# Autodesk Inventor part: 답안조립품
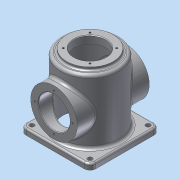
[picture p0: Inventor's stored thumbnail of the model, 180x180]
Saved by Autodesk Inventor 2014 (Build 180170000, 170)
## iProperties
Created: 2015-10
Part Number: 답안조립품
Material: 알루미늄 6061
Document SubType Name: Modeling
Designer: net
Density: 2.71 g/cm^3
Appearance: 알루미늄 - 평지
Mass: 985.994 g
Surface Area: 1037.34 cm^2
Volume: 363.835 cm^3
Author: net
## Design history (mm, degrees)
sketch "스케치1"
  geometry: L1 (60, -60)-(-60, -60); L2 (-60, -60)-(-60, 60); L3 (-60, 60)-(60, 60); L4 (60, 60)-(60, -60); L5 (60, 0)-(-60, 0); C1 r 4 at (50, -50); C2 r 4 at (-50, -50); C3 r 4 at (50, 50); C4 r 4 at (-50, 50); 2 further points
  constraints: 10 end point, 4 centre point, 3 midpoint, 2 horizontal alignment, 2 parallel, 2 perpendicular, 2 symmetric about line, 1 equal radius, 1 horizontal, 1 vertical alignment, 2 other
  dimensions: "d0" = 120 distance of L1.start L1.end; "d1" = 120 distance of L1.end L2.end; "d2" = 8 diameter of C1; "d3" = 50 horizontal distance of C1.centre point (0, 0); "d4" = 50 horizontal distance of point (0, 0) C1.centre; "d5" = 100 distance of C2.centre C1.centre
extrude "돌출1" new body sketch "스케치1" distance "d6" = 10; taper "d7" = 0 deg
fillet "모깎기1" dims "d8" = 10
node "작업 평면2"
sketch "스케치2"
  geometry: C1 r 50 at (0, 0); C2 r 40 at (0, 0); 1 further point
  constraints: 2 centre point, 2 coincident
  dimensions: "d10" = 100 diameter of C1; "d13" = 80 diameter of C2
extrude "돌출2" join sketch "스케치2" stored distance "d11" = 10; taper "d12" = 0 deg
extrude "돌출3" join sketch "스케치2" distance "d14" = 5; taper "d15" = 0 deg
hole "구멍1" diameter "d18" = 54; stored, may be unused: countersink angle "d22" = 90 deg, drill point angle "d24" = 0 deg; dims "d16" = 10, "d17" = 10, "d19" = 6, "d20" = 4, "d21" = 2, "d23" = 13
hole "구멍2" diameter "d27" = 90; stored, may be unused: countersink angle "d31" = 90 deg, drill point angle "d33" = 0 deg; dims "d25" = 10, "d26" = 10, "d28" = 6, "d29" = 4, "d30" = 2, "d32" = 112
node "작업 평면3"
sketch "스케치3"
  geometry: L1 (40, 125)-(-40, 125) reference; L2 (50, 0)-(-50, 0) reference; L3 (50, 120)-(50, 10) reference; L4 (-50, 120)-(-50, 10) reference; L5 (0, 60)-(-32.5, 60); L6 (0, 60)-(32.5, 60); C1 r 40 at (0, 60); A1 r 32.5 centre (0, 60) between (0, 92.5) and (0, 27.5); 3 further points
  constraints: 4 end point, 4 point on circle, 2 centre point, 2 midpoint, 1 coincident, 1 collinear, 1 perpendicular, 1 vertical alignment
  dimensions: "d35" = 80 diameter of C1; "d38" = 65 diameter of A1; "d82" = 60 distance from line of L2 C1.centre
extrude "돌출4" join sketch "스케치3" stored distance "d36" = 5; taper "d37" = 0 deg
hole "구멍8" sketch "스케치3" diameter "d103" = 3.242; stored, may be unused: countersink angle "d107" = 90 deg, drill point angle "d109" = 118 deg; dims "d104" = 8, "d105" = 4, "d106" = 2, "d108" = 10
hole "구멍4" diameter "d48" = 54; stored, may be unused: countersink angle "d52" = 90 deg, drill point angle "d54" = 0 deg; dims "d49" = 8, "d50" = 4, "d51" = 2, "d53" = 10, "d55" = 10, "d56" = 10
sketch "스케치4"
  geometry: L1 (0, 32.5)-(0, 0); L2 (0, 0)-(22.981, 22.981); L3 (0, 0)-(-22.981, 22.981); L4 (2.311, 0)-(32.5, 0); C1 r 40 at (0, 0) reference; A1 r 32.5 centre (0, 0) between (0, 32.5) and (22.981, 22.981); 1 further point
  constraints: 8 end point, 4 point on circle, 2 coincident, 1 centre point, 1 perpendicular, 1 vertical
  dimensions: "d57" = 65 diameter of A1; "d58" = 90 deg angle of L2 L3; "d60" = 45 deg angle of L4 L2
hole "구멍6" sketch "스케치4" at (22.981, 22.981) diameter "d70" = 3.242; stored, may be unused: countersink angle "d74" = 90 deg, drill point angle "d76" = 118 deg; dims "d71" = 8, "d72" = 4, "d73" = 2, "d75" = 10
node "작업 평면4"
sketch "스케치5"
  geometry: L1 (0, 50)-(0, -50) reference; L2 (-125, 40)-(-125, -40) reference; L3 (-100, 62)-(-20, 62) reference; 3 further points
  constraints: 1 horizontal alignment, 1 midpoint, 1 other
  dimensions: "d84" = 70 distance from line of L1 point (-70, 0)
feature "엠보싱1" sketch "스케치5" dims "d0" = 120, "d1" = 120, "d2" = 8, "d3" = 50, "d4" = 50, "d5" = 100, "d85" = 0.5, "d86" = 0
fillet "모깎기2" dims "d87" = 3, "d95" = 5
fillet "모깎기3" dims "d88" = 3
chamfer "모따기1" distance "d89" = 1; stored, may be unused: second distance "d90" = 2, angle "d91" = 45 deg
chamfer "모따기2" distance "d92" = 3; stored, may be unused: second distance "d93" = 2, angle "d94" = 45 deg
node "솔리드1"
mirror "대칭2"
pattern_circular "원형 패턴1" dims angle "d78" = 360 deg
other parameters: "d34" = 62, "d80" = -55
